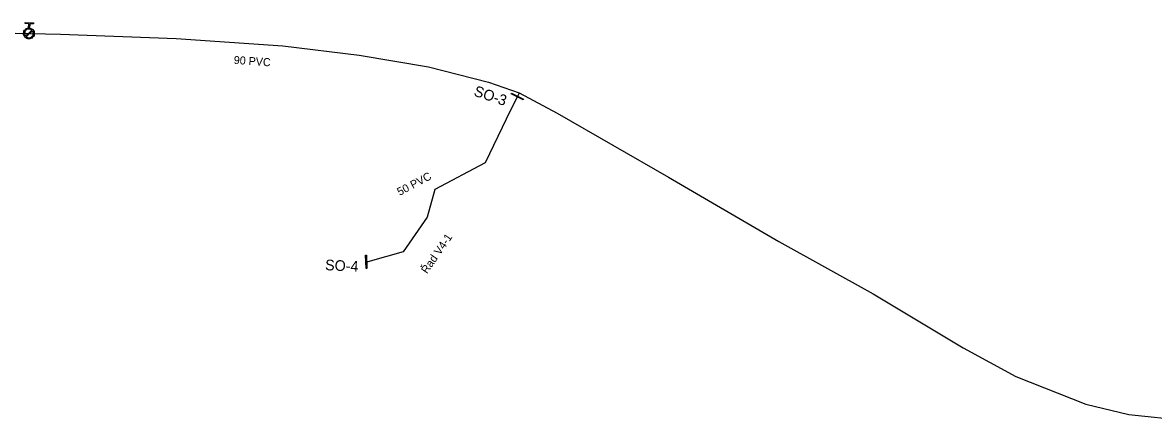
# Model space of a CAD drawing. Extents: x -553533 to -552554, y -1076883 to -1076457.
# Drawn here: x -553258.8 to -553047, y -1076800.5 to -1076726 of the extents above; entities that cross this region are included whole.
import ezdxf

# ---------------------------------------------------------------- set-up
doc = ezdxf.new("R2010")
doc.units = 0
for name, color, linetype in [('Armatura - popis', 7, 'Continuous'), ('Armatura vodovodní', 7, 'Continuous'), ('Default', 7, 'Continuous'), ('Hydrant', 7, 'Continuous'), ('Vodovodní řad', 7, 'Continuous'), ('Řad vodovodní označení', 7, 'Continuous'), ('Řad vodovodní popis', 7, 'Continuous')]:
    doc.layers.add(name, color=color, linetype=linetype)

msp = doc.modelspace()

# ---------------------------------------------------------------- linework, layer by layer
at = {"layer": 'Armatura vodovodní'}
for points in [[(-553167.21, -1076739.22), (-553164.99, -1076740.36), (-553165.06, -1076740.5), (-553167.28, -1076739.36), (-553167.21, -1076739.22)], [(-553194.42, -1076769.6), (-553194.34, -1076772.1), (-553194.5, -1076772.1), (-553194.58, -1076769.6), (-553194.42, -1076769.6)]]:
    msp.add_lwpolyline(points, dxfattribs=at)
at = {"layer": 'Default'}
for points in [[(-553257.53, -1076727.06), (-553257.17, -1076727.1), (-553256.92, -1076727.36), (-553256.64, -1076727.66), (-553256.65, -1076728.08), (-553256.66, -1076728.49), (-553256.96, -1076728.78), (-553257.26, -1076729.06), (-553257.68, -1076729.05), (-553258.09, -1076729.04), (-553258.37, -1076728.74), (-553258.66, -1076728.44), (-553258.65, -1076728.03), (-553258.64, -1076727.61), (-553258.34, -1076727.33), (-553258.08, -1076727.07), (-553257.72, -1076727.05)], [(-553257.13, -1076727.43), (-553257.34, -1076727.25), (-553257.63, -1076727.24), (-553257.97, -1076727.23), (-553258.21, -1076727.46), (-553258.45, -1076727.69), (-553258.46, -1076728.03), (-553258.47, -1076728.32), (-553258.3, -1076728.54)], [(-553258.17, -1076728.68), (-553257.96, -1076728.86), (-553257.67, -1076728.86), (-553257.34, -1076728.87), (-553257.09, -1076728.64), (-553256.85, -1076728.41), (-553256.84, -1076728.07), (-553256.83, -1076727.78), (-553257, -1076727.56)]]:
    msp.add_open_spline(points, degree=3, dxfattribs=at)
at = {"layer": 'Hydrant'}
for points in [[(-553257.72, -1076727.05), (-553257.7, -1076726.24), (-553258.38, -1076726.22), (-553258.38, -1076726.03), (-553256.82, -1076726.07), (-553256.82, -1076726.26), (-553257.51, -1076726.24), (-553257.53, -1076727.06)], [(-553258.3, -1076728.54), (-553257.13, -1076727.43)], [(-553257, -1076727.56), (-553258.17, -1076728.68)]]:
    msp.add_lwpolyline(points, dxfattribs=at)
at = {"layer": 'Vodovodní řad'}
for points in [[(-553260.26, -1076727.99), (-553251.75, -1076728.2), (-553230.05, -1076729.03), (-553210.11, -1076730.38), (-553195.81, -1076732.12), (-553182.81, -1076734.29), (-553171.55, -1076737.18), (-553165.82, -1076739.21), (-553158.66, -1076742.97), (-553137.83, -1076754.95), (-553117.17, -1076767.04), (-553099.49, -1076776.8), (-553082.61, -1076786.92), (-553072.73, -1076792.34), (-553059.61, -1076797.51), (-553051.56, -1076799.45), (-553040.76, -1076800.53)], [(-553165.81, -1076739.22), (-553166.14, -1076739.86)], [(-553166.14, -1076739.86), (-553167.44, -1076742.41), (-553172.16, -1076752.27), (-553181.63, -1076757.3), (-553183.02, -1076762.46), (-553187.51, -1076768.95), (-553194.14, -1076770.84), (-553194.46, -1076770.85)]]:
    msp.add_lwpolyline(points, dxfattribs=at)

# ---------------------------------------------------------------- texts
at = {"layer": 'Armatura - popis'}
for s, rotation, p in [('SO-3', 341.5488, (-553174.45, -1076739.68)), ('SO-4', 357.132, (-553202.2, -1076772.39))]:
    msp.add_text(s, height=2, rotation=rotation, dxfattribs=at).set_placement(p)
at = {"layer": 'Řad vodovodní označení'}
msp.add_text('Řad V4-1', height=1.5, rotation=55.3232, dxfattribs=at).set_placement((-553183.07, -1076773.18))
at = {"layer": 'Řad vodovodní popis'}
for s, rotation, p in [(' 90 PVC', 356.1268, (-553219.87, -1076733.72)), (' 50 PVC', 27.9751, (-553188.68, -1076758.77))]:
    msp.add_text(s, height=1.5, rotation=rotation, dxfattribs=at).set_placement(p)

doc.saveas('drawing.dxf')
